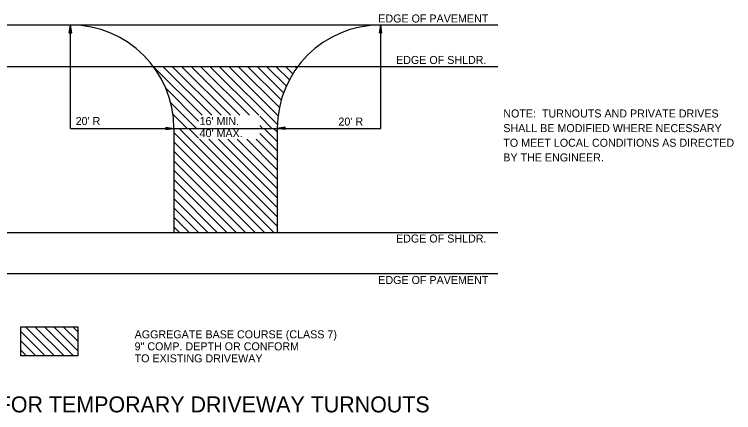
# Model space of a CAD drawing. Extents: x 1955771 to 1955918, y 566326 to 566544.
# Drawn here: x 1955813.8 to 1955867.7, y 566339.5 to 566369.4 of the extents above; entities that cross this region are included whole.
import ezdxf

# ---------------------------------------------------------------- set-up
doc = ezdxf.new("R2010")
doc.units = 0
for name, color, linetype in [('Default', 7, 'Continuous'), ('R_Grid', 7, 'Continuous'), ('R_Logo', 7, 'Continuous')]:
    doc.layers.add(name, color=color, linetype=linetype)

msp = doc.modelspace()

# ---------------------------------------------------------------- linework, layer by layer
at = {"layer": 'R_Grid'}
for p, q in [((1955817.945, 566367.972), (1955818.035, 566368.572)), ((1955817.945, 566367.972), (1955818.035, 566368.572)), ((1955817.96, 566367.972), (1955818.035, 566368.472)), ((1955817.96, 566367.972), (1955818.035, 566368.472)), ((1955817.976, 566367.972), (1955818.035, 566368.368)), ((1955817.976, 566367.972), (1955818.035, 566368.368)), ((1955817.991, 566367.972), (1955818.035, 566368.269)), ((1955817.991, 566367.972), (1955818.035, 566368.269)), ((1955818.125, 566367.972), (1955818.035, 566368.572)), ((1955818.125, 566367.972), (1955818.035, 566368.572)), ((1955818.11, 566367.972), (1955818.035, 566368.472)), ((1955818.11, 566367.972), (1955818.035, 566368.472)), ((1955818.095, 566367.972), (1955818.035, 566368.368)), ((1955818.095, 566367.972), (1955818.035, 566368.368)), ((1955818.08, 566367.972), (1955818.035, 566368.269)), ((1955818.08, 566367.972), (1955818.035, 566368.269)), ((1955841.191, 566367.972), (1955841.281, 566368.572)), ((1955841.191, 566367.972), (1955841.281, 566368.572)), ((1955841.206, 566367.972), (1955841.281, 566368.472)), ((1955841.206, 566367.972), (1955841.281, 566368.472)), ((1955841.221, 566367.972), (1955841.281, 566368.368)), ((1955841.221, 566367.972), (1955841.281, 566368.368)), ((1955841.236, 566367.972), (1955841.281, 566368.269)), ((1955841.236, 566367.972), (1955841.281, 566368.269)), ((1955841.371, 566367.972), (1955841.281, 566368.572)), ((1955841.371, 566367.972), (1955841.281, 566368.572)), ((1955841.356, 566367.972), (1955841.281, 566368.472)), ((1955841.356, 566367.972), (1955841.281, 566368.472)), ((1955841.34, 566367.972), (1955841.281, 566368.368)), ((1955841.34, 566367.972), (1955841.281, 566368.368)), ((1955841.325, 566367.972), (1955841.281, 566368.269)), ((1955841.325, 566367.972), (1955841.281, 566368.269)), ((1955817.945, 566367.972), (1955818.125, 566367.972)), ((1955817.945, 566367.972), (1955818.125, 566367.972)), ((1955818.006, 566367.972), (1955818.035, 566368.167)), ((1955818.006, 566367.972), (1955818.035, 566368.167)), ((1955818.021, 566367.972), (1955818.035, 566368.067)), ((1955818.021, 566367.972), (1955818.035, 566368.067)), ((1955818.065, 566367.972), (1955818.035, 566368.167)), ((1955818.065, 566367.972), (1955818.035, 566368.167)), ((1955818.049, 566367.972), (1955818.035, 566368.067)), ((1955818.049, 566367.972), (1955818.035, 566368.067)), ((1955841.191, 566367.972), (1955841.371, 566367.972)), ((1955841.191, 566367.972), (1955841.371, 566367.972)), ((1955841.251, 566367.972), (1955841.281, 566368.167)), ((1955841.251, 566367.972), (1955841.281, 566368.167)), ((1955841.266, 566367.972), (1955841.281, 566368.067)), ((1955841.266, 566367.972), (1955841.281, 566368.067)), ((1955841.31, 566367.972), (1955841.281, 566368.167)), ((1955841.31, 566367.972), (1955841.281, 566368.167)), ((1955841.295, 566367.972), (1955841.281, 566368.067)), ((1955841.295, 566367.972), (1955841.281, 566368.067)), ((1955825.184, 566360.913), (1955825.784, 566360.823)), ((1955825.184, 566360.913), (1955825.184, 566360.733)), ((1955825.184, 566360.913), (1955825.784, 566360.823)), ((1955825.184, 566360.913), (1955825.184, 566360.733)), ((1955825.184, 566360.898), (1955825.684, 566360.823)), ((1955825.184, 566360.898), (1955825.684, 566360.823)), ((1955825.184, 566360.883), (1955825.58, 566360.823)), ((1955825.184, 566360.883), (1955825.58, 566360.823)), ((1955825.184, 566360.868), (1955825.48, 566360.823)), ((1955825.184, 566360.868), (1955825.48, 566360.823)), ((1955825.184, 566360.853), (1955825.379, 566360.823)), ((1955825.184, 566360.853), (1955825.379, 566360.823)), ((1955825.184, 566360.838), (1955825.279, 566360.823)), ((1955825.184, 566360.838), (1955825.279, 566360.823)), ((1955825.184, 566360.733), (1955825.784, 566360.823)), ((1955825.184, 566360.794), (1955825.379, 566360.823)), ((1955825.184, 566360.764), (1955825.58, 566360.823)), ((1955825.184, 566360.748), (1955825.684, 566360.823)), ((1955825.184, 566360.779), (1955825.48, 566360.823)), ((1955825.184, 566360.809), (1955825.279, 566360.823)), ((1955825.184, 566360.733), (1955825.784, 566360.823)), ((1955825.184, 566360.794), (1955825.379, 566360.823)), ((1955825.184, 566360.764), (1955825.58, 566360.823)), ((1955825.184, 566360.748), (1955825.684, 566360.823)), ((1955825.184, 566360.779), (1955825.48, 566360.823)), ((1955825.184, 566360.809), (1955825.279, 566360.823)), ((1955834.132, 566360.913), (1955833.532, 566360.823)), ((1955834.132, 566360.913), (1955833.532, 566360.823)), ((1955834.132, 566360.733), (1955833.532, 566360.823)), ((1955834.132, 566360.733), (1955833.532, 566360.823)), ((1955834.132, 566360.898), (1955833.632, 566360.823)), ((1955834.132, 566360.898), (1955833.632, 566360.823)), ((1955834.132, 566360.748), (1955833.632, 566360.823)), ((1955834.132, 566360.748), (1955833.632, 566360.823)), ((1955834.132, 566360.883), (1955833.736, 566360.823)), ((1955834.132, 566360.883), (1955833.736, 566360.823)), ((1955834.132, 566360.764), (1955833.736, 566360.823)), ((1955834.132, 566360.764), (1955833.736, 566360.823)), ((1955834.132, 566360.868), (1955833.835, 566360.823)), ((1955834.132, 566360.868), (1955833.835, 566360.823)), ((1955834.132, 566360.779), (1955833.835, 566360.823)), ((1955834.132, 566360.779), (1955833.835, 566360.823)), ((1955834.132, 566360.853), (1955833.937, 566360.823)), ((1955834.132, 566360.853), (1955833.937, 566360.823)), ((1955834.132, 566360.794), (1955833.937, 566360.823)), ((1955834.132, 566360.794), (1955833.937, 566360.823)), ((1955834.132, 566360.838), (1955834.037, 566360.823)), ((1955834.132, 566360.838), (1955834.037, 566360.823)), ((1955834.132, 566360.809), (1955834.037, 566360.823)), ((1955834.132, 566360.809), (1955834.037, 566360.823)), ((1955834.132, 566360.733), (1955834.132, 566360.913)), ((1955834.132, 566360.733), (1955834.132, 566360.913))]:
    msp.add_line(p, q, dxfattribs=at)
at = {"layer": 'R_Logo'}
for p, q in [((1955810.274, 566368.572), (1955850.049, 566368.572)), ((1955818.035, 566360.823), (1955818.035, 566368.572)), ((1955841.281, 566360.823), (1955841.281, 566368.572)), ((1955810.274, 566365.472), (1955850.049, 566365.472)), ((1955827.909, 566361.802), (1955824.238, 566365.472)), ((1955828.616, 566361.802), (1955824.945, 566365.472)), ((1955829.323, 566361.802), (1955825.652, 566365.472)), ((1955830.03, 566361.802), (1955826.359, 566365.472)), ((1955830.737, 566361.802), (1955827.066, 566365.472)), ((1955831.444, 566361.802), (1955827.774, 566365.472)), ((1955832.151, 566361.802), (1955828.481, 566365.472)), ((1955833.543, 566361.118), (1955829.188, 566365.472)), ((1955833.595, 566361.773), (1955829.895, 566365.472)), ((1955833.693, 566362.381), (1955830.602, 566365.472)), ((1955833.832, 566362.95), (1955831.309, 566365.472)), ((1955834.005, 566363.483), (1955832.016, 566365.472)), ((1955834.21, 566363.986), (1955832.723, 566365.472)), ((1955834.442, 566364.461), (1955833.43, 566365.472)), ((1955834.701, 566364.909), (1955834.138, 566365.472)), ((1955834.984, 566365.333), (1955834.845, 566365.472)), ((1955827.635, 566361.368), (1955825.17, 566363.833)), ((1955827.473, 566360.823), (1955825.532, 566362.765)), ((1955826.766, 566360.823), (1955825.711, 566361.879)), ((1955833.13, 566360.823), (1955832.22, 566361.733)), ((1955818.035, 566360.823), (1955825.784, 566360.823)), ((1955825.784, 566360.823), (1955825.784, 566353.024)), ((1955825.784, 566360.823), (1955833.532, 566360.823)), ((1955833.532, 566353.479), (1955826.188, 566360.823)), ((1955827.635, 566360.083), (1955826.895, 566360.823)), ((1955827.635, 566360.791), (1955827.602, 566360.823)), ((1955832.423, 566360.823), (1955832.22, 566361.026)), ((1955833.532, 566359.843), (1955832.552, 566360.823)), ((1955833.532, 566360.55), (1955833.259, 566360.823)), ((1955833.532, 566360.823), (1955833.532, 566353.024)), ((1955833.532, 566360.823), (1955841.281, 566360.823)), ((1955833.281, 566353.024), (1955825.784, 566360.521)), ((1955833.532, 566359.136), (1955832.22, 566360.448)), ((1955832.574, 566353.024), (1955825.784, 566359.814)), ((1955833.532, 566354.187), (1955827.703, 566360.015)), ((1955833.532, 566354.894), (1955828.411, 566360.015)), ((1955833.532, 566355.601), (1955829.118, 566360.015)), ((1955833.532, 566356.308), (1955829.825, 566360.015)), ((1955833.532, 566357.015), (1955830.532, 566360.015)), ((1955833.532, 566357.722), (1955831.239, 566360.015)), ((1955833.532, 566358.429), (1955831.946, 566360.015)), ((1955831.867, 566353.024), (1955825.784, 566359.107)), ((1955831.16, 566353.024), (1955825.784, 566358.399)), ((1955830.453, 566353.024), (1955825.784, 566357.692)), ((1955829.745, 566353.024), (1955825.784, 566356.985)), ((1955829.038, 566353.024), (1955825.784, 566356.278)), ((1955828.331, 566353.024), (1955825.784, 566355.571)), ((1955827.624, 566353.024), (1955825.784, 566354.864)), ((1955826.917, 566353.024), (1955825.784, 566354.157)), ((1955826.21, 566353.024), (1955825.784, 566353.45)), ((1955810.274, 566353.024), (1955850.049, 566353.024)), ((1955810.274, 566349.939), (1955850.049, 566349.939)), ((1955816.142, 566343.766), (1955814.307, 566345.601)), ((1955816.849, 566343.766), (1955814.667, 566345.948)), ((1955817.556, 566343.766), (1955815.374, 566345.948)), ((1955818.263, 566343.766), (1955816.081, 566345.948)), ((1955818.588, 566344.148), (1955816.789, 566345.948)), ((1955818.588, 566344.855), (1955817.496, 566345.948)), ((1955818.588, 566345.563), (1955818.203, 566345.948)), ((1955815.435, 566343.766), (1955814.307, 566344.894)), ((1955814.728, 566343.766), (1955814.307, 566344.187))]:
    msp.add_line(p, q, dxfattribs=at)
msp.add_lwpolyline([(1955814.307, 566345.948), (1955818.588, 566345.948), (1955818.588, 566343.766), (1955814.307, 566343.766)], close=True, dxfattribs=at)
for centre, start, end in [((1955818.035, 566360.823), 0, 90), ((1955841.281, 566360.823), 90, 180)]:
    msp.add_arc(centre, 7.748, start, end, dxfattribs=at)

# ---------------------------------------------------------------- texts
at = {"layer": 'Default'}
for s, p in [('NOTE:  TURNOUTS AND PRIVATE DRIVES', (1955850.467, 566361.637)), ('SHALL BE MODIFIED WHERE NECESSARY', (1955850.467, 566360.539)), ('TO MEET LOCAL CONDITIONS AS DIRECTED', (1955850.467, 566359.442)), ('BY THE ENGINEER.', (1955850.467, 566358.344))]:
    msp.add_text(s, height=0.6, dxfattribs=at).set_placement(p)
at = {"layer": 'R_Logo'}
for s, height, p in [('EDGE OF PAVEMENT', 0.6, (1955841.099, 566368.759)), ('EDGE OF SHLDR.', 0.6, (1955842.43, 566365.651)), ("20' R", 0.6, (1955818.423, 566361.071)), ("16' MIN.", 0.6, (1955827.707, 566361.064)), ("20' R", 0.6, (1955838.114, 566361.033)), ("40' MAX.", 0.6, (1955827.707, 566360.164)), ('EDGE OF SHLDR.', 0.6, (1955842.43, 566352.26)), ('EDGE OF PAVEMENT', 0.6, (1955841.099, 566349.152)), ('AGGREGATE BASE COURSE (CLASS 7)', 0.6, (1955822.841, 566345.079)), ('9" COMP. DEPTH OR CONFORM', 0.6, (1955822.841, 566344.179)), ('TO EXISTING DRIVEWAY', 0.6, (1955822.841, 566343.279)), ('DETAIL FOR TEMPORARY DRIVEWAY TURNOUTS', 1.2, (1955806.524, 566339.526))]:
    msp.add_text(s, height=height, dxfattribs=at).set_placement(p)

doc.saveas('drawing.dxf')
